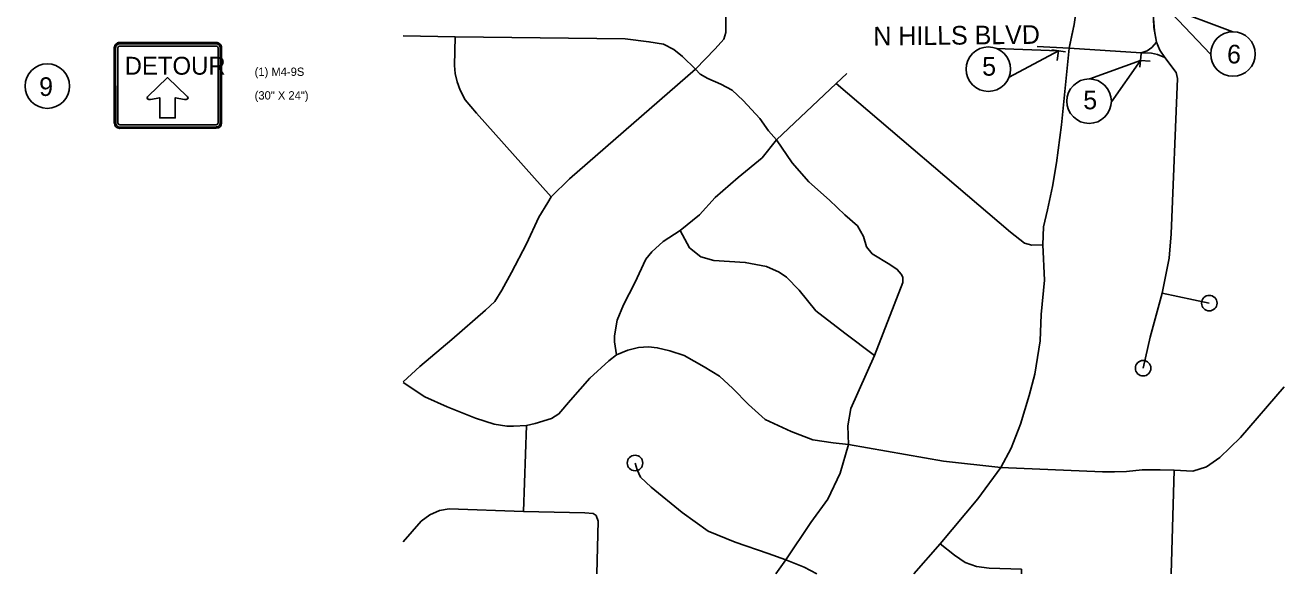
# Model space of a CAD drawing. Extents: x 185625 to 193575, y 1257500 to 1262681.
# Drawn here: x 185625 to 189658, y 1257500 to 1259263 of the extents above; entities that cross this region are included whole.
import ezdxf

# ---------------------------------------------------------------- set-up
doc = ezdxf.new("R2010")
doc.units = 0
for name, color, linetype in [('10', 7, 'Continuous'), ('8', 7, 'Continuous'), ('Level 3', 7, 'Continuous'), ('Level 8', 7, 'Continuous'), ('P_TC_Signs_Temporary', 7, 'Continuous')]:
    doc.layers.add(name, color=color, linetype=linetype)

msp = doc.modelspace()

# ---------------------------------------------------------------- linework, layer by layer
at = {"layer": '10'}
for points in [[(187883.5, 1260534.4), (187880.3, 1260032.1), (187878.6, 1259630.2), (187878.6, 1259351.3), (187877, 1259262), (187877, 1259239.2), (187870.5, 1259218.1), (187842.9, 1259187.2), (187779.5, 1259122.2), (187375.1, 1258769.8), (187316.2, 1258711.1), (187305.5, 1258693.6), (187276, 1258646.3), (187237, 1258560.8), (187188.3, 1258468.2), (187157.4, 1258411.3), (187134.7, 1258375.6), (187105.4, 1258348), (186996.6, 1258253.7), (186894.3, 1258166), (186840.7, 1258117.1)], [(188189.7, 1260404.9), (188274.2, 1260466.7), (188316.4, 1260492.6), (188344, 1260508.9), (188370, 1260512.1), (188412.2, 1260518.6), (188829.7, 1260508.9), (188852.4, 1260508.9), (188862.1, 1260507.3), (188870.3, 1260497.5), (188873.5, 1260486.1), (188873.5, 1260183.9), (188871.1, 1259848.5), (188869.5, 1259518.6), (188878.4, 1259513.8), (188922.2, 1259474.8), (188985.6, 1259414.7), (189001.8, 1259385.5), (189008.3, 1259348.1), (188997, 1259265.2), (188980.7, 1259189.6)], [(189223.2, 1259740.5), (189219.9, 1259722.6), (189218.6, 1259670.6), (189223.9, 1259591.9), (189249.2, 1259369.2), (189253.2, 1259255.3), (189261.2, 1259208.6), (189272.1, 1259183.2), (189288.7, 1259158.9), (189325.2, 1259111.3), (189329.2, 1259091.3), (189309.2, 1258593.1), (189302.5, 1258514.4), (189279.9, 1258402.4), (189241.2, 1258261), (189218.6, 1258161)], [(186840.7, 1259229.4), (187007.6, 1259226.1), (187554.1, 1259219.7), (187630.5, 1259209.9), (187677.6, 1259201.8), (187710.1, 1259185.5), (187737.7, 1259162.8), (187779.5, 1259122.2)], [(187007.6, 1259226.1), (187005.9, 1259133.5), (187007.6, 1259107.5), (187014.1, 1259081.5), (187023.8, 1259053.9), (187040, 1259023), (187075.8, 1258980.8), (187316.2, 1258711.1)], [(188760.9, 1257842.5), (188794, 1257904.6), (188824.8, 1257981), (188852.4, 1258073.6), (188870.3, 1258141.9), (188888.2, 1258249.1), (188891.4, 1258333.6), (188901.2, 1258444.1), (188896.3, 1258557.5), (188897.9, 1258614.7), (188910.9, 1258669.9), (188927.1, 1258744.7), (188940.1, 1258821), (188956.4, 1258942.9), (188980.7, 1259189.6)], [(189261.2, 1259208.6), (189246.5, 1259191.2), (189232, 1259180.7), (189212.3, 1259174.7), (188980.7, 1259189.6), (188878.3, 1259194.2)], [(189212.3, 1259174.7), (189245.9, 1259172.8), (189265, 1259168.8), (189288.7, 1259158.9)], [(187526.4, 1258203.9), (187519.7, 1258245.9), (187519.7, 1258265.4), (187527.8, 1258315.8), (187548.9, 1258364.5), (187585.1, 1258435.2), (187620.8, 1258511.5), (187639.9, 1258535.1), (187675.6, 1258567.6), (187730.9, 1258603.4), (187792.6, 1258653.7), (187842.9, 1258709), (187917.6, 1258774), (187994, 1258837.3), (188040.6, 1258894.7), (188231.9, 1259075.9), (188266.1, 1259108.4)], [(187779.5, 1259122.2), (187795.3, 1259105.9), (187819.7, 1259091.3), (187861.9, 1259073.4), (187897.7, 1259053.9), (187933.4, 1259021.4), (187987, 1258962.9), (188014.6, 1258923.9), (188040.6, 1258894.7)], [(188231.9, 1259075.9), (188792.3, 1258598.2), (188837.8, 1258562.4), (188860.5, 1258555.9), (188896.3, 1258557.5)], [(188040.6, 1258894.7), (188090.6, 1258821), (188144.2, 1258759.3), (188210.8, 1258700.8), (188259.6, 1258653.7), (188300.2, 1258617.9), (188319.7, 1258583.8), (188329.4, 1258551.3), (188347.3, 1258528.6), (188404.1, 1258494.5), (188428.5, 1258478.2), (188441.5, 1258463.6), (188446.3, 1258453.8), (188446.3, 1258436), (188355.4, 1258202), (188279, 1258031.4), (188269.3, 1257976.1), (188271.6, 1257915.9)], [(188355.4, 1258202), (188259.6, 1258273.5), (188167, 1258345), (188113.4, 1258411.6), (188072.8, 1258453.8), (188048.4, 1258470.1), (188007.8, 1258488), (187939.6, 1258501), (187838.9, 1258507.5), (187796.6, 1258518.8), (187760.9, 1258548.1), (187730.9, 1258603.4)], [(189279.9, 1258402.4), (189431.3, 1258370)], [(189671.8, 1258101.1), (189531.9, 1257938.4), (189465.2, 1257874.5), (189422.5, 1257843.8), (189378.5, 1257830.5), (189318.1, 1257833.2), (189273.2, 1257834.5), (189215.9, 1257834.5), (189165.2, 1257829.1), (189126.2, 1257827.8), (189087.9, 1257827.8), (188760.9, 1257842.5), (188576.9, 1257862.5), (188271.6, 1257915.9), (188222.3, 1257921.2), (188157, 1257930.5), (188087.6, 1257957.2), (188003.6, 1257995.9), (187950.3, 1258043.9), (187899.7, 1258095.9), (187857, 1258135.9), (187807.7, 1258165.3), (187743.7, 1258201.3), (187697, 1258217.3), (187657, 1258226.6), (187629, 1258229.3), (187597, 1258227.9), (187562.4, 1258218.6), (187526.4, 1258203.9)], [(186840.7, 1258114.6), (186910.6, 1258069.3), (186982.1, 1258036.8), (187073, 1258001), (187133.1, 1257981.5), (187173.7, 1257975), (187194.8, 1257975), (187237.1, 1257976.6), (187264.7, 1257983.1), (187316.7, 1257999.4), (187341, 1258014), (187378.4, 1258057.9), (187440.1, 1258129.4), (187501.8, 1258184.6), (187526.4, 1258203.9)], [(187237.1, 1257976.6), (187227.3, 1257700.4)], [(188038, 1257500.1), (188069.8, 1257545.5), (188151, 1257664.8), (188205.2, 1257740.7), (188245, 1257823.8), (188271.6, 1257915.9)], [(187585.6, 1257856.4), (187592.8, 1257834.7), (187603.6, 1257811.2), (187638, 1257778.7), (187737.3, 1257697.3), (187820.4, 1257637.7), (187907.2, 1257601.6), (188013.7, 1257565.4), (188069.8, 1257545.5), (188129.4, 1257522), (188169.9, 1257500.1)], [(188760.9, 1257842.5), (188687.3, 1257740.8), (188566.2, 1257596.3), (188481.8, 1257500.1)], [(189318.1, 1257833.2), (189308.9, 1257500.1)], [(186840.7, 1257602.6), (186898.5, 1257669.9), (186926.2, 1257689.4), (186957, 1257704), (186987.9, 1257708.9), (187227.3, 1257700.4), (187424.8, 1257695.9), (187450.8, 1257694.2), (187460.5, 1257687.7), (187467, 1257669.9), (187463.3, 1257500.1)], [(188566.2, 1257596.3), (188612.8, 1257560.5), (188647.1, 1257536.2), (188683.5, 1257524.1), (188724, 1257518), (188828.2, 1257514.9)], [(188828.2, 1257500.1), (188828.2, 1257514.9)]]:
    msp.add_lwpolyline(points, dxfattribs=at)
for centre in [(189431.3, 1258370), (189218.6, 1258161), (187585.6, 1257856.4)]:
    msp.add_circle(centre, 25, dxfattribs=at)
at = {"layer": 'Level 3'}
for p, q in [((188925, 1259184.4), (188969.5, 1259177.6)), ((188947, 1259180.4), (188942.4, 1259150)), ((189207.9, 1259127.7), (189212.1, 1259172.5)), ((189210.7, 1259149.9), (189241.2, 1259147))]:
    msp.add_line(p, q, dxfattribs=at)
at = {"layer": 'Level 8'}
for points in [[(189435.6, 1259170), (189289, 1259322.8), (189507.1, 1259241.5)], [(188997, 1259265.2), (188989.6, 1259230.8), (188980.8, 1259189.7), (189212.3, 1259174.7), (189232, 1259180.7), (189246.5, 1259191.2), (189261.2, 1259208.6), (189255, 1259245.2), (189252.2, 1259284.7)], [(188787.9, 1259096.4), (188947.1, 1259181), (188746.5, 1259188.7)], [(189116.5, 1259016.8), (189210, 1259150), (189047.2, 1259090.4)]]:
    msp.add_lwpolyline(points, dxfattribs=at)
for centre in [(189507.2, 1259170.4), (188721.1, 1259121.8), (185696.8, 1259067.3), (189045, 1259019)]:
    msp.add_circle(centre, 71.5, dxfattribs=at)
at = {"layer": 'P_TC_Signs_Temporary'}
for p, q in [((185912, 1259190.2), (185912.1, 1258948.8)), ((185916.4, 1259190.2), (185916.5, 1258948.8)), ((185923.5, 1259190.2), (185923.6, 1258948.8)), ((186239.7, 1259207.6), (185929.3, 1259207.4)), ((186239.7, 1259203.2), (185929.3, 1259203.1)), ((186239.7, 1259196.1), (185929.3, 1259195.9)), ((186245.5, 1258948.9), (186245.4, 1259190.3)), ((186252.7, 1258948.9), (186252.6, 1259190.3)), ((186257, 1258948.9), (186256.9, 1259190.3)), ((185929.4, 1258943), (186239.8, 1258943.2)), ((185929.4, 1258935.8), (186239.8, 1258936)), ((185929.4, 1258931.5), (186239.8, 1258931.7))]:
    msp.add_line(p, q, dxfattribs=at)
for points in [[(186146.3, 1259034.3), (186083.2, 1259094.5), (186020.3, 1259034.3)], [(186028.8, 1259024.4), (186058.3, 1259029.9), (186058.3, 1258965.2), (186108.1, 1258965.2), (186108.1, 1259029.9), (186137.5, 1259024.3)]]:
    msp.add_lwpolyline(points, dxfattribs=at)
for centre, radius, start, end in [((185929.3, 1259190.2), 17.2, 90.0233, 180.0233), ((185929.3, 1259190.2), 12.9, 90.0233, 180.0233), ((185929.3, 1259190.2), 5.75, 90.0233, 180.0233), ((186239.7, 1259190.3), 17.2, 0.0233, 90.0233), ((186239.7, 1259190.3), 12.9, 0.0233, 90.0233), ((186239.7, 1259190.3), 5.75, 0.0233, 90.0233), ((185929.4, 1258948.8), 17.2, 180.0233, 270.0233), ((185929.4, 1258948.8), 12.9, 180.0233, 270.0233), ((185929.4, 1258948.8), 5.75, 180.0233, 270.0233), ((186239.8, 1258948.9), 12.9, 270.0233, 0.0233), ((186239.8, 1258948.9), 5.75, 270.0233, 0.0233), ((186239.8, 1258948.9), 17.2, 270.0233, 0.0233)]:
    msp.add_arc(centre, radius, start, end, dxfattribs=at)
for centre, major_axis, start_param, end_param in [((186026.4, 1259029.8), (-9.03, 0), 5.701809, 8.132695), ((185249.5, 1259348.9), (920.5, 0), 5.701809, 5.70473), ((186140.1, 1259029.8), (9.2, 0), 4.433676, 6.865934), ((186916.3, 1259349.6), (-920.5, 0), 0.579949, 0.582749)]:
    msp.add_ellipse(centre, major_axis=major_axis, ratio=0.625, start_param=start_param, end_param=end_param, dxfattribs=at)

# ---------------------------------------------------------------- texts
at = {"layer": '8'}
for s, height, p in [('(1) M4-9S', 26.85, (186363.1, 1259100.1)), ('(30" X 24")', 26.847, (186363.1, 1259024.1))]:
    msp.add_text(s, height=height, rotation=0.0007, dxfattribs=at).set_placement(p)
at = {"layer": 'Level 8'}
for s, rotation, p in [('N HILLS BLVD', 0.622, (188351.9, 1259197.7)), ('6', 357.5832, (189487.3, 1259141.2)), ('9', 359.6134, (185670.3, 1259035.9))]:
    msp.add_text(s, height=60, rotation=rotation, dxfattribs=at).set_placement(p)
for p in [(188701.3, 1259100.9), (189026.2, 1258992.9)]:
    msp.add_text('5', height=60, dxfattribs=at).set_placement(p)
at = {"layer": 'P_TC_Signs_Temporary'}
msp.add_text('DETOUR', height=57.48, rotation=0.0233, dxfattribs=at).set_placement((185945.3, 1259104))

doc.saveas('drawing.dxf')
